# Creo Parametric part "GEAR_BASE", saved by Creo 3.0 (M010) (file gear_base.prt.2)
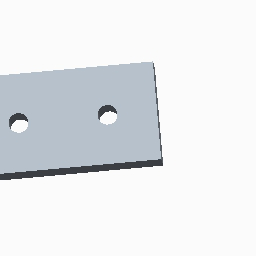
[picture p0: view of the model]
Units: millimeter Newton Second (mmNs); MM, TONNE, SECS

Created from: INLBS_PART_SOLID.PRT

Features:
  1. datum plane "RIGHT"
  2. datum plane "TOP"
  3. datum plane "FRONT"
  4. coordinate system
  5. extrusion "Extrude 1"

Surfaces: 9 plane, 4 cylinder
